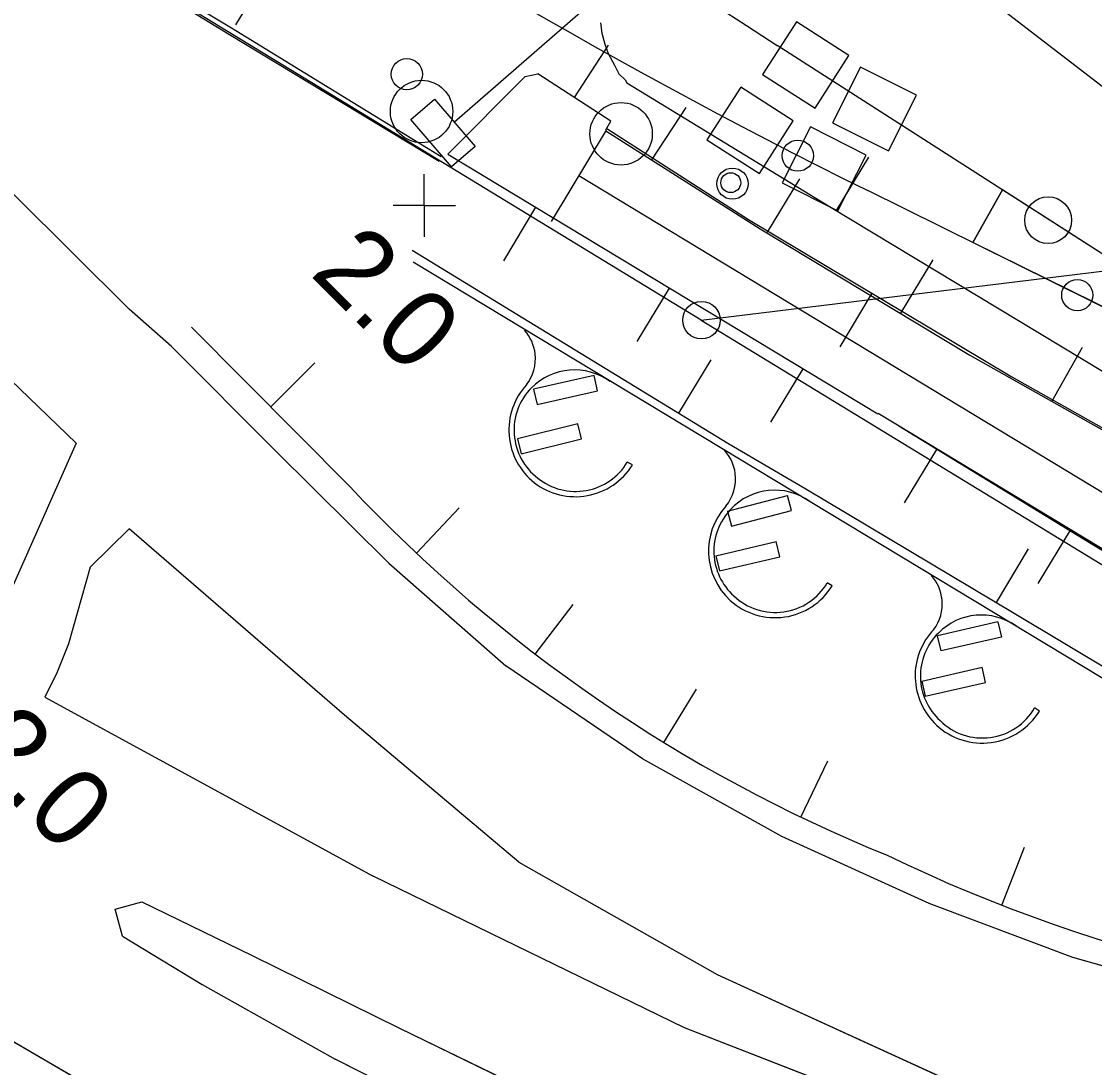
# Model space of a CAD drawing. Extents: x 1596643 to 1597288, y 13057194 to 13057957.
# Drawn here: x 1596850.68 to 1596885.06, y 13057439.15 to 13057472.66 of the extents above; entities that cross this region are included whole.
import ezdxf

# ---------------------------------------------------------------- set-up
doc = ezdxf.new("R2010")
doc.units = 0
for name, color, linetype in [('A spårmitt L', 7, 'Continuous'), ('B Fsk P', 7, 'Continuous'), ('B kabelbrunn mindre än 150 cm NK P', 7, 'Continuous'), ('B växel linjevikt 0 L', 7, 'Continuous'), ('BAS byggnad anläggning L', 7, 'Continuous'), ('BAS fastighetsgräns samfällighet L', 7, 'Continuous'), ('BAS gränspunkt P', 7, 'Continuous'), ('BAS Level 15', 7, 'Continuous'), ('BAS Level 16', 7, 'Continuous'), ('BAS Level 18', 7, 'Continuous'), ('BAS Level 29', 7, 'Continuous'), ('BAS Level 37', 7, 'Continuous'), ('BAS Level 63', 7, 'Continuous'), ('BAS markytetext T', 7, 'Continuous'), ('BAS skärmtak L', 7, 'Continuous'), ('BAS stödmur fot L', 7, 'Continuous'), ('BAS stödmur krön L', 7, 'Continuous'), ('BAS trappa L', 7, 'Continuous'), ('BAS vägbanekant L', 7, 'Continuous'), ('D Plattform L', 7, 'Continuous'), ('E ktlbrygga L', 7, 'Continuous'), ('E ktlstolpe omvriden centrum P', 7, 'Continuous'), ('F balis P', 7, 'Continuous'), ('F signal fristående P', 7, 'Continuous'), ('F vägskyddsanordning stolpe driv P', 7, 'Continuous')]:
    doc.layers.add(name, color=color, linetype=linetype)

msp = doc.modelspace()

# ---------------------------------------------------------------- linework, layer by layer
at = {"layer": 'A spårmitt L'}
msp.add_line((1596908.746, 13057450.177), (1596874.893, 13057471.888), dxfattribs=at)
for points in [[(1596901.218, 13057459.344), (1596886.823, 13057469.398), (1596871.343, 13057481.319)], [(1596896.843, 13057457.811), (1596877.793, 13057467.24)]]:
    msp.add_lwpolyline(points, dxfattribs=at)
for centre, radius, start, end in [((1597037.43, 13057725.326), 301.08, 223.02589, 237.32659), ((1596962.077, 13057637.523), 190, 226.32199, 243.66622)]:
    msp.add_arc(centre, radius, start, end, dxfattribs=at)
msp.add_spline([(1596921.486, 13057453.819), (1596905.281, 13057468.17), (1596896.354, 13057476.52), (1596877.996, 13057494.854)], degree=3, dxfattribs=at)
at = {"layer": 'B Fsk P'}
msp.add_circle((1596883.57, 13057466.293), 0.75, dxfattribs=at)
msp.add_circle((1596883.57, 13057466.293), 0.75, dxfattribs=at)
at = {"layer": 'B kabelbrunn mindre än 150 cm NK P'}
for centre in [(1596863.023, 13057470.969), (1596863.023, 13057470.969), (1596873.455, 13057467.463), (1596873.455, 13057467.463)]:
    msp.add_circle(centre, 0.5, dxfattribs=at)
at = {"layer": 'B växel linjevikt 0 L'}
for p, q in [((1596882.111, 13057467.263), (1596881.159, 13057465.581)), ((1596882.111, 13057467.263), (1596881.159, 13057465.581)), ((1596881.159, 13057465.581), (1596882.111, 13057467.263)), ((1596882.111, 13057467.263), (1596881.159, 13057465.581)), ((1596896.82, 13057457.828), (1596882.111, 13057467.263)), ((1596896.82, 13057457.828), (1596882.111, 13057467.263)), ((1596896.82, 13057457.828), (1596882.111, 13057467.263)), ((1596896.82, 13057457.828), (1596881.159, 13057465.581)), ((1596896.82, 13057457.828), (1596881.159, 13057465.581))]:
    msp.add_line(p, q, dxfattribs=at)
at = {"layer": 'BAS byggnad anläggning L'}
for p, q in [((1596870.251, 13057458.453), (1596870.089, 13057458.543)), ((1596876.654, 13057454.582), (1596876.493, 13057454.681)), ((1596883.292, 13057450.573), (1596883.137, 13057450.674))]:
    msp.add_line(p, q, dxfattribs=at)
for centre, radius, start, end in [((1596865.776, 13057461.856), 1.37, 6.4548, 41.7364), ((1596865.776, 13057461.862), 1.37, 322.299, 6.2097), ((1596868.389, 13057459.569), 1.93, 53.5988, 135.3264), ((1596868.445, 13057459.572), 2.15, 137.5184, 231.731), ((1596868.39, 13057459.57), 1.93, 135.3601, 232.8041), ((1596872.187, 13057458.008), 1.37, 7.2549, 42.1296), ((1596868.434, 13057459.536), 1.93, 231.1568, 329.0282), ((1596868.425, 13057459.588), 2.15, 232.4266, 328.1348), ((1596872.187, 13057458.008), 1.37, 320.2983, 7.2485), ((1596874.81, 13057455.717), 1.93, 54.2107, 137.2711), ((1596874.842, 13057455.698), 2.15, 138.1255, 227.4498), ((1596874.79, 13057455.696), 1.93, 136.416, 228.0957), ((1596878.806, 13057454.006), 1.37, 5.3482, 41.439), ((1596874.825, 13057455.713), 2.15, 228.0432, 328.2661), ((1596874.83, 13057455.66), 1.93, 226.5107, 329.5113), ((1596878.807, 13057453.998), 1.37, 323.5644, 5.7111), ((1596881.431, 13057451.717), 1.93, 54.4071, 135.5179), ((1596881.46, 13057451.695), 2.15, 136.1622, 227.018), ((1596881.408, 13057451.694), 1.93, 134.5315, 227.664), ((1596881.466, 13057451.639), 1.93, 225.3064, 329.9865), ((1596881.458, 13057451.696), 2.15, 227.062, 328.5117)]:
    msp.add_arc(centre, radius, start, end, dxfattribs=at)
at = {"layer": 'BAS fastighetsgräns samfällighet L'}
msp.add_lwpolyline([(1596872.455, 13057463.088), (1596929.415, 13057470.053)], dxfattribs=at)
at = {"layer": 'BAS gränspunkt P'}
for centre, radius in [((1596872.463, 13057463.093), 0.6), ((1596872.463, 13057463.093), 0.6), ((1596872.456, 13057463.088), 0.001), ((1596872.456, 13057463.088), 0.001)]:
    msp.add_circle(centre, radius, dxfattribs=at)
at = {"layer": 'BAS Level 15'}
for centre in [(1596875.55, 13057468.36), (1596875.55, 13057468.36), (1596884.504, 13057463.894), (1596884.504, 13057463.894)]:
    msp.add_circle(centre, 0.5, dxfattribs=at)
at = {"layer": 'BAS Level 16'}
for q in [(1596863.582, 13057467.765), (1596863.582, 13057467.765), (1596862.582, 13057466.765), (1596862.582, 13057466.765), (1596864.582, 13057466.765), (1596863.582, 13057465.765), (1596864.582, 13057466.765), (1596863.582, 13057465.765)]:
    msp.add_line((1596863.582, 13057466.765), q, dxfattribs=at)
at = {"layer": 'BAS Level 18'}
for p, q in [((1596868.392, 13057470.227), (1596869.482, 13057471.904)), ((1596868.392, 13057470.227), (1596869.482, 13057471.904)), ((1596870.875, 13057468.227), (1596871.969, 13057469.901)), ((1596870.875, 13057468.227), (1596871.969, 13057469.901)), ((1596877.812, 13057468.318), (1596876.78, 13057466.605)), ((1596877.812, 13057468.318), (1596876.78, 13057466.605)), ((1596874.579, 13057465.91), (1596875.617, 13057467.62)), ((1596874.579, 13057465.91), (1596875.617, 13057467.62)), ((1596867.151, 13057466.707), (1596866.117, 13057464.995)), ((1596867.151, 13057466.707), (1596866.117, 13057464.995)), ((1596878.853, 13057463.316), (1596879.891, 13057465.026)), ((1596878.853, 13057463.316), (1596879.891, 13057465.026)), ((1596871.431, 13057464.122), (1596870.397, 13057462.41)), ((1596871.431, 13057464.122), (1596870.397, 13057462.41)), ((1596877.92, 13057463.954), (1596876.894, 13057462.237)), ((1596877.92, 13057463.954), (1596876.894, 13057462.237)), ((1596883.689, 13057460.486), (1596884.675, 13057462.226)), ((1596883.689, 13057460.486), (1596884.675, 13057462.226)), ((1596858.664, 13057460.319), (1596860.083, 13057461.728)), ((1596858.664, 13057460.319), (1596860.083, 13057461.728)), ((1596872.769, 13057461.821), (1596871.726, 13057460.115)), ((1596872.769, 13057461.821), (1596871.726, 13057460.115)), ((1596875.711, 13057461.537), (1596874.677, 13057459.825)), ((1596875.711, 13057461.537), (1596874.677, 13057459.825)), ((1596879.991, 13057458.953), (1596878.957, 13057457.241)), ((1596879.991, 13057458.953), (1596878.957, 13057457.241)), ((1596863.331, 13057455.629), (1596864.702, 13057457.085)), ((1596863.331, 13057455.629), (1596864.702, 13057457.085)), ((1596884.271, 13057456.368), (1596883.237, 13057454.656)), ((1596884.271, 13057456.368), (1596883.237, 13057454.656)), ((1596882.932, 13057455.77), (1596881.907, 13057454.053)), ((1596882.932, 13057455.77), (1596881.907, 13057454.053)), ((1596867.141, 13057452.395), (1596868.356, 13057453.984)), ((1596867.141, 13057452.395), (1596868.356, 13057453.984)), ((1596871.262, 13057449.567), (1596872.308, 13057451.272)), ((1596871.262, 13057449.567), (1596872.308, 13057451.272)), ((1596875.651, 13057447.176), (1596876.517, 13057448.979)), ((1596875.651, 13057447.176), (1596876.517, 13057448.979)), ((1596882.09, 13057444.353), (1596882.815, 13057446.217)), ((1596882.09, 13057444.353), (1596882.815, 13057446.217))]:
    msp.add_line(p, q, dxfattribs=at)
for points in [[(1596869.233, 13057472.62), (1596869.273, 13057472.284), (1596869.373, 13057471.928), (1596869.474, 13057471.633), (1596869.676, 13057471.256), (1596869.817, 13057470.982), (1596870.02, 13057470.788), (1596870.07, 13057470.696), (1596876.571, 13057466.731), (1596886.714, 13057460.618), (1596889.27, 13057459.15)], [(1596863.194, 13057465.33), (1596873.304, 13057459.15)], [(1596873.304, 13057459.15), (1596875.811, 13057457.691), (1596882.485, 13057453.708), (1596893.896, 13057446.874), (1596894.027, 13057446.528)]]:
    msp.add_lwpolyline(points, dxfattribs=at)
at = {"layer": 'BAS Level 29'}
msp.add_circle((1596873.403, 13057467.496), 0.318, dxfattribs=at)
msp.add_circle((1596873.403, 13057467.496), 0.318, dxfattribs=at)
at = {"layer": 'BAS Level 37'}
for points in [[(1596872.455, 13057463.088), (1596840.526, 13057482.557)], [(1596872.455, 13057463.088), (1596878.914, 13057459.15)], [(1596878.914, 13057459.15), (1596920.541, 13057433.769), (1596934.167, 13057425.381), (1596938.443, 13057422.802), (1596956.991, 13057405.807)]]:
    msp.add_lwpolyline(points, dxfattribs=at)
at = {"layer": 'BAS Level 63'}
msp.add_line((1596864.181, 13057469.084), (1596864.181, 13057469.084), dxfattribs=at)
at = {"layer": 'BAS skärmtak L'}
for p, q in [((1596869.023, 13057461.316), (1596867.084, 13057460.885)), ((1596869.131, 13057460.828), (1596869.023, 13057461.316)), ((1596867.084, 13057460.885), (1596867.202, 13057460.389)), ((1596867.202, 13057460.389), (1596869.131, 13057460.828)), ((1596868.506, 13057459.774), (1596866.569, 13057459.294)), ((1596868.626, 13057459.289), (1596868.506, 13057459.774)), ((1596866.569, 13057459.294), (1596866.689, 13057458.809)), ((1596866.689, 13057458.809), (1596868.626, 13057459.289)), ((1596873.302, 13057456.977), (1596875.225, 13057457.481)), ((1596875.352, 13057456.997), (1596875.225, 13057457.481)), ((1596873.302, 13057456.977), (1596873.429, 13057456.493)), ((1596873.429, 13057456.493), (1596875.352, 13057456.997)), ((1596872.923, 13057455.544), (1596874.857, 13057456.002)), ((1596874.973, 13057455.516), (1596874.857, 13057456.003)), ((1596872.923, 13057455.544), (1596873.039, 13057455.058)), ((1596873.039, 13057455.058), (1596874.973, 13057455.516)), ((1596881.962, 13057453.428), (1596880.026, 13057452.983)), ((1596881.962, 13057453.428), (1596882.074, 13057452.941)), ((1596880.138, 13057452.496), (1596880.026, 13057452.983)), ((1596882.074, 13057452.941), (1596880.138, 13057452.496)), ((1596879.523, 13057451.531), (1596881.453, 13057451.975)), ((1596881.565, 13057451.488), (1596881.453, 13057451.975)), ((1596879.523, 13057451.531), (1596879.635, 13057451.044)), ((1596879.635, 13057451.044), (1596881.565, 13057451.488))]:
    msp.add_line(p, q, dxfattribs=at)
at = {"layer": 'BAS stödmur fot L'}
for p, q in [((1596864.335, 13057468.408), (1596866.817, 13057470.901)), ((1596866.817, 13057470.901), (1596867.226, 13057470.985)), ((1596869.558, 13057469.469), (1596867.226, 13057470.985)), ((1596869.401, 13057469.189), (1596869.558, 13057469.469)), ((1596864.335, 13057468.408), (1596878.111, 13057460.088)), ((1596893.69, 13057446.559), (1596863.227, 13057464.952))]:
    msp.add_line(p, q, dxfattribs=at)
for points in [[(1596801.38, 13057521.802), (1596807.902, 13057515.293), (1596815.586, 13057507.536), (1596822.317, 13057500.788), (1596829.481, 13057493.571), (1596836.802, 13057486.17), (1596840.401, 13057482.599), (1596850.573, 13057476.382), (1596857.34, 13057472.24), (1596864.058, 13057468.19)], [(1596869.397, 13057469.159), (1596874.346, 13057466.016), (1596881.06, 13057461.974), (1596891.601, 13057456.034)], [(1596878.129, 13057460.111), (1596886.781, 13057454.877), (1596895.436, 13057449.654), (1596898.551, 13057447.748)]]:
    msp.add_lwpolyline(points, dxfattribs=at)
at = {"layer": 'BAS stödmur krön L'}
msp.add_line((1596861.197, 13057457.767), (1596856.131, 13057462.871), dxfattribs=at)
for points in [[(1596864.123, 13057468.328), (1596857.409, 13057472.44), (1596850.653, 13057476.515), (1596840.554, 13057482.67), (1596836.91, 13057486.331), (1596829.604, 13057493.672), (1596822.422, 13057500.909), (1596815.38, 13057507.962), (1596808.004, 13057515.412), (1596801.503, 13057521.945)], [(1596869.429, 13057469.233), (1596873.974, 13057466.314), (1596882.404, 13057461.272), (1596891.584, 13057456.105), (1596894.279, 13057455.482), (1596897.513, 13057454.611), (1596901.314, 13057453.101)], [(1596878.787, 13057459.703), (1596884.705, 13057456.09), (1596894.812, 13057449.952), (1596898.489, 13057447.759)]]:
    msp.add_lwpolyline(points, dxfattribs=at)
for centre, radius, start, end in [((1596896.766, 13057491.149), 48.78, 223.1833, 247.8992), ((1596900.529, 13057491.753), 50.86, 244.2248, 270.1611)]:
    msp.add_arc(centre, radius, start, end, dxfattribs=at)
at = {"layer": 'BAS trappa L'}
msp.add_line((1596869.416, 13057469.177), (1596867.648, 13057466.255), dxfattribs=at)
msp.add_lwpolyline([(1596899.981, 13057450.473), (1596890.028, 13057454.706), (1596868.532, 13057467.716)], dxfattribs=at)
at = {"layer": 'BAS vägbanekant L'}
for p, q in [((1596855.481, 13057462.251), (1596858.83, 13057458.893)), ((1596858.83, 13057458.893), (1596862.448, 13057455.309)), ((1596854.133, 13057456.409), (1596852.879, 13057455.184)), ((1596861.026, 13057450.441), (1596854.133, 13057456.409)), ((1596852.879, 13057455.184), (1596852.188, 13057452.722)), ((1596862.448, 13057455.309), (1596866.193, 13057452.023)), ((1596852.188, 13057452.722), (1596851.825, 13057451.821)), ((1596870.576, 13057449.041), (1596866.193, 13057452.023)), ((1596851.825, 13057451.821), (1596851.433, 13057451.015)), ((1596875.039, 13057446.554), (1596870.576, 13057449.041)), ((1596879.755, 13057444.413), (1596875.039, 13057446.554)), ((1596853.68, 13057444.222), (1596854.533, 13057444.462)), ((1596854.533, 13057444.462), (1596858.07, 13057442.738)), ((1596853.921, 13057443.365), (1596853.68, 13057444.222)), ((1596884.358, 13057442.682), (1596879.755, 13057444.413)), ((1596853.921, 13057443.365), (1596856.466, 13057441.818)), ((1596858.07, 13057442.738), (1596862.787, 13057440.419)), ((1596889.488, 13057441.236), (1596884.358, 13057442.682)), ((1596872.969, 13057442.133), (1596881.661, 13057438.16)), ((1596856.466, 13057441.818), (1596860.724, 13057439.418)), ((1596855.549, 13057436.991), (1596847.714, 13057441.55)), ((1596862.787, 13057440.419), (1596868.003, 13057437.881)), ((1596881.802, 13057436.577), (1596871.924, 13057440.426)), ((1596865.144, 13057437.195), (1596860.724, 13057439.418))]:
    msp.add_line(p, q, dxfattribs=at)
for points in [[(1596855.481, 13057462.251), (1596854.127, 13057463.442), (1596848.649, 13057468.875), (1596841.763, 13057475.747), (1596835.201, 13057482.353), (1596829.337, 13057488.194), (1596822.512, 13057495.126), (1596819.302, 13057498.393)], [(1596852.428, 13057459.15), (1596844.301, 13057466.976), (1596843.835, 13057467.384), (1596843.632, 13057467.345), (1596843.428, 13057467.274), (1596843.285, 13057467.143), (1596843.254, 13057467.072), (1596843.613, 13057461.563), (1596843.882, 13057459.15)], [(1596855.481, 13057462.251), (1596858.83, 13057458.893)], [(1596852.428, 13057459.15), (1596849.945, 13057453.565), (1596848.453, 13057454.077), (1596846.879, 13057454.539), (1596845.924, 13057454.705), (1596844.573, 13057454.923), (1596844.228, 13057454.913), (1596844.004, 13057454.945), (1596843.913, 13057455.097), (1596843.884, 13057455.341), (1596843.887, 13057456.378), (1596843.922, 13057457.881), (1596843.904, 13057458.623), (1596843.882, 13057459.15)], [(1596858.83, 13057458.893), (1596862.448, 13057455.309)], [(1596854.133, 13057456.409), (1596852.879, 13057455.184)], [(1596861.026, 13057450.441), (1596854.133, 13057456.409)], [(1596852.879, 13057455.184), (1596852.188, 13057452.722)], [(1596862.448, 13057455.309), (1596866.193, 13057452.023)], [(1596852.188, 13057452.722), (1596851.825, 13057451.821)], [(1596870.576, 13057449.041), (1596866.193, 13057452.023)], [(1596851.825, 13057451.821), (1596851.433, 13057451.015)], [(1596851.433, 13057451.015), (1596861.943, 13057445.287)], [(1596866.616, 13057445.732), (1596861.026, 13057450.441)], [(1596875.039, 13057446.554), (1596870.576, 13057449.041)], [(1596879.755, 13057444.413), (1596875.039, 13057446.554)], [(1596866.616, 13057445.732), (1596872.969, 13057442.133)], [(1596871.924, 13057440.426), (1596861.943, 13057445.287)], [(1596853.68, 13057444.222), (1596854.533, 13057444.462)], [(1596854.533, 13057444.462), (1596858.07, 13057442.738)], [(1596853.921, 13057443.365), (1596853.68, 13057444.222)], [(1596884.358, 13057442.682), (1596879.755, 13057444.413)], [(1596853.921, 13057443.365), (1596856.466, 13057441.818)], [(1596858.07, 13057442.738), (1596862.787, 13057440.419)], [(1596889.488, 13057441.236), (1596884.358, 13057442.682)], [(1596872.969, 13057442.133), (1596881.661, 13057438.16)], [(1596856.466, 13057441.818), (1596860.724, 13057439.418)], [(1596855.549, 13057436.991), (1596847.714, 13057441.55)], [(1596862.787, 13057440.419), (1596868.003, 13057437.881)], [(1596881.802, 13057436.577), (1596871.924, 13057440.426)], [(1596865.144, 13057437.195), (1596860.724, 13057439.418)]]:
    msp.add_lwpolyline(points, dxfattribs=at)
at = {"layer": 'D Plattform L'}
msp.add_line((1596859.324, 13057475.498), (1596857.539, 13057472.547), dxfattribs=at)
at = {"layer": 'E ktlbrygga L'}
msp.add_lwpolyline([(1596878.954, 13057481.979), (1596864.552, 13057469.43)], dxfattribs=at)
at = {"layer": 'E ktlstolpe omvriden centrum P'}
msp.add_lwpolyline([(1596863.15, 13057469.517), (1596863.909, 13057470.168), (1596865.212, 13057468.651), (1596864.453, 13057468)], close=True, dxfattribs=at)
at = {"layer": 'F balis P'}
for p, q in [((1596875.504, 13057472.65), (1596874.424, 13057470.966)), ((1596875.504, 13057472.65), (1596874.424, 13057470.966)), ((1596877.188, 13057471.57), (1596875.504, 13057472.65)), ((1596877.188, 13057471.57), (1596875.504, 13057472.65)), ((1596875.806, 13057471.268), (1596875.806, 13057471.268)), ((1596875.806, 13057471.268), (1596875.806, 13057471.268)), ((1596876.108, 13057469.886), (1596877.188, 13057471.57)), ((1596876.108, 13057469.886), (1596877.188, 13057471.57)), ((1596874.424, 13057470.966), (1596876.108, 13057469.886)), ((1596874.424, 13057470.966), (1596876.108, 13057469.886)), ((1596877.559, 13057471.197), (1596876.662, 13057469.408)), ((1596877.559, 13057471.197), (1596876.662, 13057469.408)), ((1596879.348, 13057470.3), (1596877.559, 13057471.197)), ((1596879.348, 13057470.3), (1596877.559, 13057471.197)), ((1596873.721, 13057470.555), (1596872.641, 13057468.871)), ((1596873.721, 13057470.555), (1596872.641, 13057468.871)), ((1596875.405, 13057469.475), (1596873.721, 13057470.555)), ((1596875.405, 13057469.475), (1596873.721, 13057470.555)), ((1596878.451, 13057468.511), (1596879.348, 13057470.3)), ((1596878.451, 13057468.511), (1596879.348, 13057470.3)), ((1596878.005, 13057469.854), (1596878.005, 13057469.854)), ((1596878.005, 13057469.854), (1596878.005, 13057469.854)), ((1596874.325, 13057467.791), (1596875.405, 13057469.475)), ((1596874.325, 13057467.791), (1596875.405, 13057469.475)), ((1596875.952, 13057469.282), (1596875.05, 13057467.496)), ((1596875.952, 13057469.282), (1596875.05, 13057467.496)), ((1596877.738, 13057468.38), (1596875.952, 13057469.282)), ((1596877.738, 13057468.38), (1596875.952, 13057469.282)), ((1596876.662, 13057469.408), (1596878.451, 13057468.511)), ((1596876.662, 13057469.408), (1596878.451, 13057468.511)), ((1596872.641, 13057468.871), (1596874.325, 13057467.791)), ((1596872.641, 13057468.871), (1596874.325, 13057467.791)), ((1596874.023, 13057469.173), (1596874.023, 13057469.173)), ((1596874.023, 13057469.173), (1596874.023, 13057469.173)), ((1596876.836, 13057466.594), (1596877.738, 13057468.38)), ((1596876.836, 13057466.594), (1596877.738, 13057468.38)), ((1596876.394, 13057467.938), (1596876.394, 13057467.938)), ((1596876.394, 13057467.938), (1596876.394, 13057467.938)), ((1596875.05, 13057467.496), (1596876.836, 13057466.594)), ((1596875.05, 13057467.496), (1596876.836, 13057466.594))]:
    msp.add_line(p, q, dxfattribs=at)
at = {"layer": 'F signal fristående P'}
msp.add_circle((1596863.497, 13057469.776), 1, dxfattribs=at)
msp.add_circle((1596863.497, 13057469.776), 1, dxfattribs=at)
at = {"layer": 'F vägskyddsanordning stolpe driv P'}
msp.add_circle((1596869.89, 13057469.061), 1, dxfattribs=at)
msp.add_circle((1596869.89, 13057469.061), 1, dxfattribs=at)

# ---------------------------------------------------------------- texts
at = {"layer": 'BAS markytetext T'}
for p in [(1596859.883, 13057464.565), (1596848.773, 13057449.229)]:
    msp.add_text('2.0', height=2.5, rotation=315, dxfattribs=at).set_placement(p)

doc.saveas('drawing.dxf')
